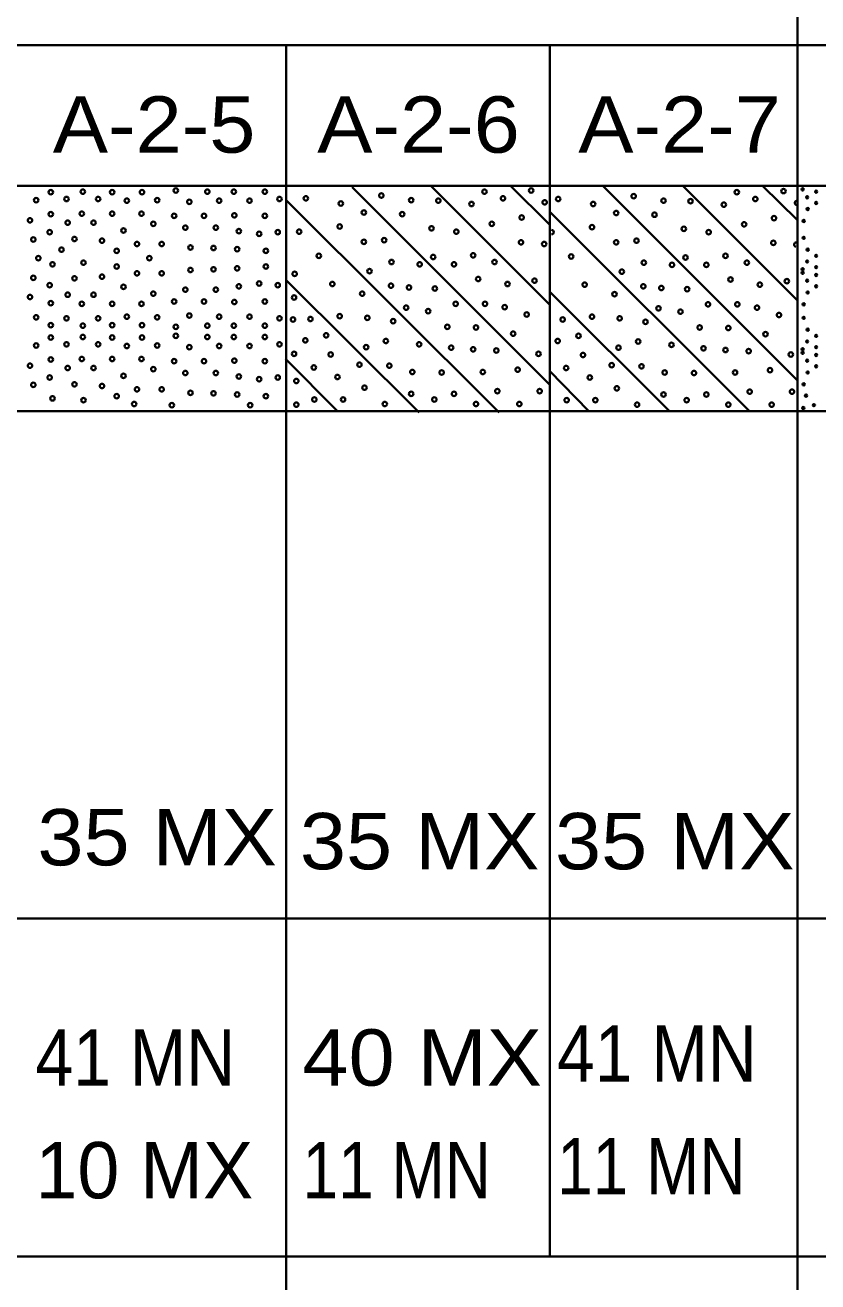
# Model space of a CAD drawing. Extents: x 2137492.6 to 2137529.1, y 2137475.8 to 2137563.
# Drawn here: x 2137496 to 2137497.407, y 2137553.178 to 2137555.408 of the extents above; entities that cross this region are included whole.
import ezdxf
from ezdxf.enums import TextEntityAlignment as Align

# ---------------------------------------------------------------- set-up
doc = ezdxf.new("R2010")
doc.units = 0
doc.header["$LTSCALE"] = 0.04
doc.layers.add('1', color=7, linetype='Continuous', lineweight=35)

msp = doc.modelspace()

# ---------------------------------------------------------------- linework, layer by layer
at = {"layer": '1'}
for p, q in [((2137497.371, 2137556.123), (2137497.371, 2137551.631)), ((2137494.121, 2137555.373), (2137499.271, 2137555.373)), ((2137496.463, 2137552.923), (2137496.463, 2137555.374)), ((2137496.931, 2137553.223), (2137496.931, 2137555.374)), ((2137493.171, 2137555.123), (2137501.871, 2137555.123)), ((2137496.58, 2137555.121), (2137496.93, 2137554.771)), ((2137496.721, 2137555.122), (2137496.93, 2137554.913)), ((2137496.861, 2137555.124), (2137496.93, 2137555.055)), ((2137497.025, 2137555.123), (2137497.37, 2137554.778)), ((2137497.167, 2137555.123), (2137497.37, 2137554.92)), ((2137497.309, 2137555.123), (2137497.37, 2137555.063)), ((2137496.841, 2137554.721), (2137496.463, 2137555.098)), ((2137497.285, 2137554.724), (2137496.931, 2137555.077)), ((2137496.699, 2137554.721), (2137496.463, 2137554.956)), ((2137497.143, 2137554.724), (2137496.931, 2137554.935)), ((2137496.554, 2137554.723), (2137496.462, 2137554.816)), ((2137497, 2137554.724), (2137496.931, 2137554.794)), ((2137493.171, 2137554.723), (2137501.871, 2137554.723)), ((2137493.171, 2137553.823), (2137501.871, 2137553.823)), ((2137493.171, 2137553.223), (2137499.271, 2137553.223))]:
    msp.add_line(p, q, dxfattribs=at)
msp.add_lwpolyline([(2137497.371, 2137555.123), (2137497.867, 2137555.123), (2137497.867, 2137554.723), (2137497.371, 2137554.723)], close=True, dxfattribs=at)
for centre, radius in [((2137496.04506, 2137555.11186), 0.004), ((2137496.10206, 2137555.11286), 0.004), ((2137496.15406, 2137555.11186), 0.004), ((2137496.20706, 2137555.11186), 0.004), ((2137496.26706, 2137555.11486), 0.004), ((2137496.32306, 2137555.11286), 0.004), ((2137496.37006, 2137555.11286), 0.004), ((2137496.42506, 2137555.11286), 0.004), ((2137496.81506, 2137555.11286), 0.004), ((2137496.89806, 2137555.11486), 0.004), ((2137497.26306, 2137555.11186), 0.004), ((2137497.34606, 2137555.11386), 0.004), ((2137497.38006, 2137555.11686), 0.002), ((2137497.40406, 2137555.11286), 0.002), ((2137496.01906, 2137555.09786), 0.004), ((2137496.07306, 2137555.09986), 0.004), ((2137496.12906, 2137555.09986), 0.004), ((2137496.18006, 2137555.09686), 0.004), ((2137496.23406, 2137555.09786), 0.004), ((2137496.29106, 2137555.09486), 0.004), ((2137496.34406, 2137555.09686), 0.004), ((2137496.39806, 2137555.09686), 0.004), ((2137496.45106, 2137555.09986), 0.004), ((2137496.49806, 2137555.10086), 0.004), ((2137496.56006, 2137555.09186), 0.004), ((2137496.63206, 2137555.10586), 0.004), ((2137496.68506, 2137555.09786), 0.004), ((2137496.73306, 2137555.09686), 0.004), ((2137496.79206, 2137555.09086), 0.004), ((2137496.84806, 2137555.10086), 0.004), ((2137496.92206, 2137555.09386), 0.004), ((2137496.94606, 2137555.09986), 0.004), ((2137497.00806, 2137555.09086), 0.004), ((2137497.08006, 2137555.10486), 0.004), ((2137497.13306, 2137555.09686), 0.004), ((2137497.18106, 2137555.09586), 0.004), ((2137497.24006, 2137555.08986), 0.004), ((2137497.29606, 2137555.09986), 0.004), ((2137497.38806, 2137555.10286), 0.002), ((2137497.40406, 2137555.09286), 0.002), ((2137496.04506, 2137555.07286), 0.004), ((2137496.10006, 2137555.07386), 0.004), ((2137496.15406, 2137555.07386), 0.004), ((2137496.20606, 2137555.07386), 0.004), ((2137496.26406, 2137555.06986), 0.004), ((2137496.31706, 2137555.06986), 0.004), ((2137496.37106, 2137555.07086), 0.004), ((2137496.42506, 2137555.06986), 0.004), ((2137496.60106, 2137555.07586), 0.004), ((2137496.66906, 2137555.07286), 0.004), ((2137496.88106, 2137555.06686), 0.004), ((2137497.04906, 2137555.07486), 0.004), ((2137497.11706, 2137555.07186), 0.004), ((2137497.32906, 2137555.06586), 0.004), ((2137497.38906, 2137555.08186), 0.002), ((2137496.00806, 2137555.06186), 0.004), ((2137496.07506, 2137555.05786), 0.004), ((2137496.12106, 2137555.05786), 0.004), ((2137496.17406, 2137555.04386), 0.004), ((2137496.22706, 2137555.05586), 0.004), ((2137496.28406, 2137555.04886), 0.004), ((2137496.33806, 2137555.04886), 0.004), ((2137496.55806, 2137555.05086), 0.004), ((2137496.72106, 2137555.04786), 0.004), ((2137496.82806, 2137555.05586), 0.004), ((2137497.00606, 2137555.04986), 0.004), ((2137497.16906, 2137555.04686), 0.004), ((2137497.27606, 2137555.05486), 0.004), ((2137497.38206, 2137555.06086), 0.002), ((2137496.01406, 2137555.02786), 0.004), ((2137496.04306, 2137555.04086), 0.004), ((2137496.08706, 2137555.02886), 0.004), ((2137496.13606, 2137555.02586), 0.004), ((2137496.37906, 2137555.04286), 0.004), ((2137496.41506, 2137555.03786), 0.004), ((2137496.44806, 2137555.04086), 0.004), ((2137496.48606, 2137555.04186), 0.004), ((2137496.60106, 2137555.02386), 0.004), ((2137496.63706, 2137555.02686), 0.004), ((2137496.76506, 2137555.04186), 0.004), ((2137496.88006, 2137555.02286), 0.004), ((2137497.04906, 2137555.02286), 0.004), ((2137497.08506, 2137555.02586), 0.004), ((2137497.21306, 2137555.04086), 0.004), ((2137497.32806, 2137555.02186), 0.004), ((2137497.38206, 2137555.03086), 0.002), ((2137496.06406, 2137555.00986), 0.004), ((2137496.16206, 2137555.00786), 0.004), ((2137496.19806, 2137555.01986), 0.004), ((2137496.24206, 2137555.01986), 0.004), ((2137496.29306, 2137555.01386), 0.004), ((2137496.33406, 2137555.01286), 0.004), ((2137496.37606, 2137555.01086), 0.004), ((2137496.42706, 2137555.00786), 0.004), ((2137496.52106, 2137554.99886), 0.004), ((2137496.79506, 2137554.99986), 0.004), ((2137496.92106, 2137555.01986), 0.004), ((2137497.24306, 2137554.99886), 0.004), ((2137497.38906, 2137555.00986), 0.002), ((2137496.02306, 2137554.99486), 0.004), ((2137496.04806, 2137554.98386), 0.004), ((2137496.10306, 2137554.98686), 0.004), ((2137496.16206, 2137554.97986), 0.004), ((2137496.22006, 2137554.99486), 0.004), ((2137496.37606, 2137554.97686), 0.004), ((2137496.42706, 2137554.97986), 0.004), ((2137496.65006, 2137554.98786), 0.004), ((2137496.70006, 2137554.98386), 0.004), ((2137496.72406, 2137554.99686), 0.004), ((2137496.76106, 2137554.98386), 0.004), ((2137496.83306, 2137554.98786), 0.004), ((2137496.96906, 2137554.99786), 0.004), ((2137497.09806, 2137554.98686), 0.004), ((2137497.14806, 2137554.98286), 0.004), ((2137497.17206, 2137554.99586), 0.004), ((2137497.20906, 2137554.98286), 0.004), ((2137497.28106, 2137554.98686), 0.004), ((2137497.38806, 2137554.98886), 0.002), ((2137497.40406, 2137554.99886), 0.002), ((2137497.40406, 2137554.97886), 0.002), ((2137496.01406, 2137554.95986), 0.004), ((2137496.08706, 2137554.95886), 0.004), ((2137496.13606, 2137554.96186), 0.004), ((2137496.19806, 2137554.96786), 0.004), ((2137496.24206, 2137554.96786), 0.004), ((2137496.29306, 2137554.97386), 0.004), ((2137496.33406, 2137554.97486), 0.004), ((2137496.47806, 2137554.96686), 0.004), ((2137496.61106, 2137554.97186), 0.004), ((2137496.80406, 2137554.95786), 0.004), ((2137496.90406, 2137554.95486), 0.004), ((2137497.05906, 2137554.97086), 0.004), ((2137497.25206, 2137554.95686), 0.004), ((2137497.38006, 2137554.97486), 0.002), ((2137497.38006, 2137554.96886), 0.002), ((2137497.40406, 2137554.96486), 0.002), ((2137496.04306, 2137554.94686), 0.004), ((2137496.17406, 2137554.94386), 0.004), ((2137496.28406, 2137554.93886), 0.004), ((2137496.33806, 2137554.93886), 0.004), ((2137496.37906, 2137554.94486), 0.004), ((2137496.41506, 2137554.94986), 0.004), ((2137496.44806, 2137554.94686), 0.004), ((2137496.54506, 2137554.94886), 0.004), ((2137496.64906, 2137554.94586), 0.004), ((2137496.68106, 2137554.94286), 0.004), ((2137496.72706, 2137554.94086), 0.004), ((2137496.85606, 2137554.94886), 0.004), ((2137496.99306, 2137554.94786), 0.004), ((2137497.09706, 2137554.94486), 0.004), ((2137497.12906, 2137554.94186), 0.004), ((2137497.17506, 2137554.93986), 0.004), ((2137497.30406, 2137554.94786), 0.004), ((2137497.35206, 2137554.95386), 0.004), ((2137497.38806, 2137554.95486), 0.002), ((2137497.40406, 2137554.94486), 0.002), ((2137496.00806, 2137554.92586), 0.004), ((2137496.04506, 2137554.91486), 0.004), ((2137496.07506, 2137554.92986), 0.004), ((2137496.10006, 2137554.91386), 0.004), ((2137496.12106, 2137554.92986), 0.004), ((2137496.15406, 2137554.91386), 0.004), ((2137496.20606, 2137554.91386), 0.004), ((2137496.22706, 2137554.93186), 0.004), ((2137496.26406, 2137554.91786), 0.004), ((2137496.31706, 2137554.91786), 0.004), ((2137496.37106, 2137554.91686), 0.004), ((2137496.42506, 2137554.91786), 0.004), ((2137496.47706, 2137554.92486), 0.004), ((2137496.59806, 2137554.93186), 0.004), ((2137496.76406, 2137554.91386), 0.004), ((2137496.81606, 2137554.91386), 0.004), ((2137497.04606, 2137554.93086), 0.004), ((2137497.21206, 2137554.91286), 0.004), ((2137497.26406, 2137554.91286), 0.004), ((2137497.38206, 2137554.91286), 0.002), ((2137497.38906, 2137554.93386), 0.002), ((2137496.01906, 2137554.88986), 0.004), ((2137496.07306, 2137554.88786), 0.004), ((2137496.12906, 2137554.88786), 0.004), ((2137496.18006, 2137554.89086), 0.004), ((2137496.23406, 2137554.88986), 0.004), ((2137496.29106, 2137554.89286), 0.004), ((2137496.34406, 2137554.89086), 0.004), ((2137496.39806, 2137554.89086), 0.004), ((2137496.45106, 2137554.88786), 0.004), ((2137496.55806, 2137554.89186), 0.004), ((2137496.60706, 2137554.88886), 0.004), ((2137496.67606, 2137554.90686), 0.004), ((2137496.71506, 2137554.90086), 0.004), ((2137496.85106, 2137554.90786), 0.004), ((2137496.89006, 2137554.89486), 0.004), ((2137497.00606, 2137554.89086), 0.004), ((2137497.05506, 2137554.88786), 0.004), ((2137497.12406, 2137554.90586), 0.004), ((2137497.16306, 2137554.89986), 0.004), ((2137497.29906, 2137554.90686), 0.004), ((2137497.33806, 2137554.89386), 0.004), ((2137496.04506, 2137554.87586), 0.004), ((2137496.10206, 2137554.87486), 0.004), ((2137496.15406, 2137554.87586), 0.004), ((2137496.20706, 2137554.87586), 0.004), ((2137496.26706, 2137554.87286), 0.004), ((2137496.32306, 2137554.87486), 0.004), ((2137496.37006, 2137554.87486), 0.004), ((2137496.42506, 2137554.87486), 0.004), ((2137496.47506, 2137554.88586), 0.004), ((2137496.50606, 2137554.88686), 0.004), ((2137496.65306, 2137554.88286), 0.004), ((2137496.74906, 2137554.87286), 0.004), ((2137496.80006, 2137554.87186), 0.004), ((2137496.95406, 2137554.88586), 0.004), ((2137497.10106, 2137554.88186), 0.004), ((2137497.19706, 2137554.87186), 0.004), ((2137497.24806, 2137554.87086), 0.004), ((2137497.38206, 2137554.88886), 0.002), ((2137497.38906, 2137554.86786), 0.002), ((2137496.04506, 2137554.85386), 0.004), ((2137496.10206, 2137554.85486), 0.004), ((2137496.15406, 2137554.85386), 0.004), ((2137496.20706, 2137554.85386), 0.004), ((2137496.26706, 2137554.85686), 0.004), ((2137496.32306, 2137554.85486), 0.004), ((2137496.37006, 2137554.85486), 0.004), ((2137496.42506, 2137554.85486), 0.004), ((2137496.49706, 2137554.84886), 0.004), ((2137496.53406, 2137554.85786), 0.004), ((2137496.64006, 2137554.84786), 0.004), ((2137496.86606, 2137554.86086), 0.004), ((2137496.94506, 2137554.84786), 0.004), ((2137496.98206, 2137554.85686), 0.004), ((2137497.08806, 2137554.84686), 0.004), ((2137497.31406, 2137554.85986), 0.004), ((2137497.38806, 2137554.84686), 0.002), ((2137497.40406, 2137554.85686), 0.002), ((2137496.01906, 2137554.83986), 0.004), ((2137496.07306, 2137554.84186), 0.004), ((2137496.12906, 2137554.84186), 0.004), ((2137496.18006, 2137554.83886), 0.004), ((2137496.23406, 2137554.83986), 0.004), ((2137496.29106, 2137554.83686), 0.004), ((2137496.34406, 2137554.83886), 0.004), ((2137496.39806, 2137554.83886), 0.004), ((2137496.45106, 2137554.84186), 0.004), ((2137496.47706, 2137554.82486), 0.004), ((2137496.54206, 2137554.82386), 0.004), ((2137496.60506, 2137554.83686), 0.004), ((2137496.69906, 2137554.84186), 0.004), ((2137496.75606, 2137554.83586), 0.004), ((2137496.79506, 2137554.83286), 0.004), ((2137496.83606, 2137554.83086), 0.004), ((2137496.91106, 2137554.82486), 0.004), ((2137496.99006, 2137554.82286), 0.004), ((2137497.05306, 2137554.83586), 0.004), ((2137497.14706, 2137554.84086), 0.004), ((2137497.20406, 2137554.83486), 0.004), ((2137497.24306, 2137554.83186), 0.004), ((2137497.28406, 2137554.82986), 0.004), ((2137497.35906, 2137554.82386), 0.004), ((2137497.38006, 2137554.83286), 0.002), ((2137497.38006, 2137554.82686), 0.002), ((2137497.40406, 2137554.83686), 0.002), ((2137497.40406, 2137554.82286), 0.002), ((2137496.00806, 2137554.80386), 0.004), ((2137496.04506, 2137554.81486), 0.004), ((2137496.07506, 2137554.79986), 0.004), ((2137496.10006, 2137554.81586), 0.004), ((2137496.12106, 2137554.79986), 0.004), ((2137496.15406, 2137554.81586), 0.004), ((2137496.20606, 2137554.81586), 0.004), ((2137496.26406, 2137554.81186), 0.004), ((2137496.31706, 2137554.81186), 0.004), ((2137496.37106, 2137554.81286), 0.004), ((2137496.42506, 2137554.81186), 0.004), ((2137496.51206, 2137554.80086), 0.004), ((2137496.59306, 2137554.80586), 0.004), ((2137496.64606, 2137554.80386), 0.004), ((2137496.96006, 2137554.79986), 0.004), ((2137497.04106, 2137554.80486), 0.004), ((2137497.09406, 2137554.80286), 0.004), ((2137497.38806, 2137554.81286), 0.002), ((2137497.40406, 2137554.80286), 0.002), ((2137496.04306, 2137554.78286), 0.004), ((2137496.17406, 2137554.78586), 0.004), ((2137496.22706, 2137554.79786), 0.004), ((2137496.28406, 2137554.79086), 0.004), ((2137496.33806, 2137554.79086), 0.004), ((2137496.37906, 2137554.78486), 0.004), ((2137496.41506, 2137554.77986), 0.004), ((2137496.44806, 2137554.78286), 0.004), ((2137496.48106, 2137554.77686), 0.004), ((2137496.55406, 2137554.78386), 0.004), ((2137496.68706, 2137554.79286), 0.004), ((2137496.73906, 2137554.79186), 0.004), ((2137496.81206, 2137554.79286), 0.004), ((2137496.87406, 2137554.79686), 0.004), ((2137497.00206, 2137554.78286), 0.004), ((2137497.13506, 2137554.79186), 0.004), ((2137497.18706, 2137554.79086), 0.004), ((2137497.26006, 2137554.79186), 0.004), ((2137497.32206, 2137554.79586), 0.004), ((2137497.38906, 2137554.79186), 0.002), ((2137496.01406, 2137554.76986), 0.004), ((2137496.08706, 2137554.77086), 0.004), ((2137496.13606, 2137554.76786), 0.004), ((2137496.19806, 2137554.76186), 0.004), ((2137496.24206, 2137554.76186), 0.004), ((2137496.29306, 2137554.75586), 0.004), ((2137496.33406, 2137554.75486), 0.004), ((2137496.60206, 2137554.76486), 0.004), ((2137496.68506, 2137554.75386), 0.004), ((2137496.76106, 2137554.75386), 0.004), ((2137496.83806, 2137554.75886), 0.004), ((2137496.91306, 2137554.75886), 0.004), ((2137497.05006, 2137554.76386), 0.004), ((2137497.28606, 2137554.75786), 0.004), ((2137497.36106, 2137554.75786), 0.004), ((2137497.38206, 2137554.77086), 0.002), ((2137496.04806, 2137554.74586), 0.004), ((2137496.10306, 2137554.74286), 0.004), ((2137496.16206, 2137554.74986), 0.004), ((2137496.19306, 2137554.73586), 0.004), ((2137496.26006, 2137554.73386), 0.004), ((2137496.37606, 2137554.75286), 0.004), ((2137496.39906, 2137554.73386), 0.004), ((2137496.42706, 2137554.74986), 0.004), ((2137496.48106, 2137554.73486), 0.004), ((2137496.51306, 2137554.74386), 0.004), ((2137496.56406, 2137554.74386), 0.004), ((2137496.63806, 2137554.73586), 0.004), ((2137496.72606, 2137554.74386), 0.004), ((2137496.80006, 2137554.73586), 0.004), ((2137496.87706, 2137554.73586), 0.004), ((2137496.96106, 2137554.74286), 0.004), ((2137497.01206, 2137554.74286), 0.004), ((2137497.08606, 2137554.73486), 0.004), ((2137497.13306, 2137554.75286), 0.004), ((2137497.17406, 2137554.74286), 0.004), ((2137497.20906, 2137554.75286), 0.004), ((2137497.24806, 2137554.73486), 0.004), ((2137497.32506, 2137554.73486), 0.004), ((2137497.38606, 2137554.75086), 0.002), ((2137497.40006, 2137554.73386), 0.002), ((2137497.38106, 2137554.72886), 0.002)]:
    msp.add_circle(centre, radius, dxfattribs=at)
for centre, start, end in [((2137497.37006, 2137555.09286), 71.56505, 261.86989), ((2137496.93406, 2137555.04086), 270, 90), ((2137497.36906, 2137555.01886), 90, 255.06858)]:
    msp.add_arc(centre, 0.004, start, end, dxfattribs=at)

# ---------------------------------------------------------------- texts
at = {"layer": '1', "width": 1.1}
for s, p in [('A-2-5', (2137496.2285, 2137555.182)), ('A-2-6', (2137496.698, 2137555.182)), ('A-2-7', (2137497.1615, 2137555.182)), ('35 MX', (2137496.234, 2137553.917)), ('35 MX', (2137496.7, 2137553.91)), ('35 MX', (2137497.153, 2137553.91))]:
    msp.add_text(s, height=0.1, dxfattribs=at).set_placement(p, align=Align.CENTER)
at = {"layer": '1'}
for s, width, p in [('41 MN', 0.9, (2137496.018, 2137553.526)), ('40 MX', 1.1, (2137496.492, 2137553.526)), ('41 MN', 0.9, (2137496.944, 2137553.533)), ('11 MN', 0.85, (2137496.492, 2137553.326)), ('11 MN', 0.85, (2137496.944, 2137553.333))]:
    msp.add_text(s, height=0.1, dxfattribs=dict(at, width=width)).set_placement(p)
msp.add_text('10 MX', height=0.1, dxfattribs=at).set_placement((2137496.018, 2137553.326))

doc.saveas('drawing.dxf')
